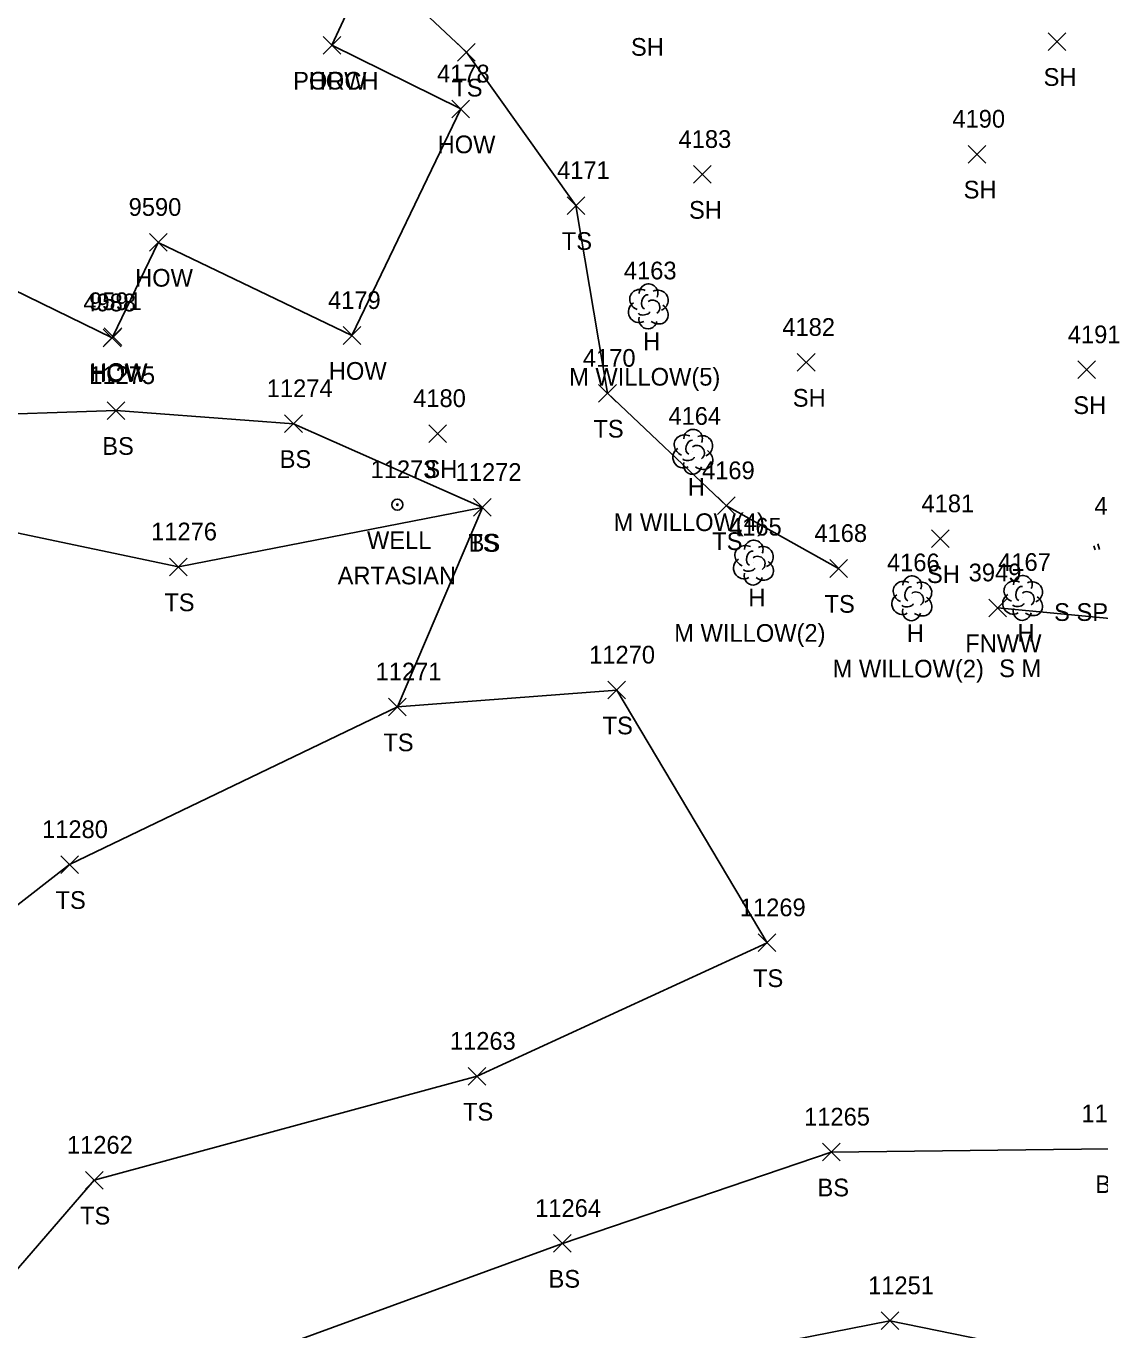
# Model space of a CAD drawing. Extents: x 1482574 to 1485769, y 580696 to 595649.
# Drawn here: x 1483580.3 to 1483701.6, y 583220.6 to 583367.9 of the extents above; entities that cross this region are included whole.
import ezdxf

# ---------------------------------------------------------------- set-up
doc = ezdxf.new("R2010")
doc.units = 0
for name, color, linetype in [('L_A', 7, 'Continuous'), ('L_C', 7, 'Continuous'), ('L_I', 7, 'Continuous'), ('L_TIC', 7, 'Continuous'), ('LBC', 7, 'Continuous'), ('LBF', 7, 'Continuous'), ('LELB', 7, 'Continuous'), ('LFNC', 7, 'Continuous'), ('LTC', 7, 'Continuous'), ('LTD', 7, 'Continuous'), ('U_A', 7, 'Continuous'), ('U_C', 7, 'Continuous'), ('U_I', 7, 'Continuous'), ('UWW', 7, 'Continuous')]:
    doc.layers.add(name, color=color, linetype=linetype)

msp = doc.modelspace()

# ---------------------------------------------------------------- linework, layer by layer
at = {"layer": 'L_TIC'}
for points in [[(1483613.84, 583364.72), (1483615.84, 583366.72)], [(1483615.84, 583364.72), (1483613.84, 583366.72)], [(1483613.84, 583364.72), (1483615.84, 583366.72)], [(1483615.84, 583364.72), (1483613.84, 583366.72)], [(1483695.74, 583365.14), (1483697.74, 583367.14)], [(1483697.74, 583365.14), (1483695.74, 583367.14)], [(1483629.03, 583363.94), (1483631.03, 583365.94)], [(1483631.03, 583363.94), (1483629.03, 583365.94)], [(1483628.4, 583357.53), (1483630.4, 583359.53)], [(1483630.4, 583357.53), (1483628.4, 583359.53)], [(1483686.71, 583352.42), (1483688.71, 583354.42)], [(1483688.71, 583352.42), (1483686.71, 583354.42)], [(1483655.69, 583350.13), (1483657.69, 583352.13)], [(1483657.69, 583350.13), (1483655.69, 583352.13)], [(1483641.4, 583346.61), (1483643.4, 583348.61)], [(1483643.4, 583346.61), (1483641.4, 583348.61)], [(1483594.22, 583342.46), (1483596.22, 583344.46)], [(1483596.22, 583342.46), (1483594.22, 583344.46)], [(1483589.02, 583331.67), (1483591.02, 583333.67)], [(1483591.02, 583331.67), (1483589.02, 583333.67)], [(1483589.11, 583331.81), (1483591.11, 583333.81)], [(1483591.11, 583331.81), (1483589.11, 583333.81)], [(1483616.11, 583331.94), (1483618.11, 583333.94)], [(1483618.11, 583331.94), (1483616.11, 583333.94)], [(1483667.41, 583328.9), (1483669.41, 583330.9)], [(1483669.41, 583328.9), (1483667.41, 583330.9)], [(1483699.1, 583328.07), (1483701.1, 583330.07)], [(1483701.1, 583328.07), (1483699.1, 583330.07)], [(1483644.97, 583325.41), (1483646.97, 583327.41)], [(1483646.97, 583325.41), (1483644.97, 583327.41)], [(1483589.46, 583323.46), (1483591.46, 583325.46)], [(1483591.46, 583323.46), (1483589.46, 583325.46)], [(1483609.5, 583321.98), (1483611.5, 583323.98)], [(1483611.5, 583321.98), (1483609.5, 583323.98)], [(1483625.8, 583320.87), (1483627.8, 583322.86)], [(1483627.8, 583320.87), (1483625.8, 583322.86)], [(1483630.84, 583312.52), (1483632.84, 583314.52)], [(1483632.84, 583312.52), (1483630.84, 583314.52)], [(1483630.84, 583312.52), (1483632.84, 583314.52)], [(1483632.84, 583312.52), (1483630.84, 583314.52)], [(1483658.4, 583312.71), (1483660.39, 583314.71)], [(1483660.39, 583312.71), (1483658.4, 583314.71)], [(1483682.57, 583308.98), (1483684.57, 583310.98)], [(1483684.57, 583308.98), (1483682.57, 583310.98)], [(1483596.5, 583305.8), (1483598.5, 583307.8)], [(1483598.5, 583305.8), (1483596.5, 583307.8)], [(1483671.09, 583305.62), (1483673.08, 583307.62)], [(1483673.08, 583305.62), (1483671.09, 583307.62)], [(1483689.03, 583301.17), (1483691.03, 583303.17)], [(1483691.03, 583301.17), (1483689.03, 583303.17)], [(1483646.01, 583291.89), (1483648.01, 583293.89)], [(1483648.01, 583291.89), (1483646.01, 583293.89)], [(1483621.24, 583289.98), (1483623.24, 583291.98)], [(1483623.24, 583289.98), (1483621.24, 583291.98)], [(1483621.24, 583289.98), (1483623.24, 583291.98)], [(1483623.24, 583289.98), (1483621.24, 583291.98)], [(1483584.21, 583272.17), (1483586.21, 583274.17)], [(1483586.21, 583272.17), (1483584.21, 583274.17)], [(1483663, 583263.34), (1483665, 583265.34)], [(1483665, 583263.34), (1483663, 583265.34)], [(1483630.24, 583248.26), (1483632.24, 583250.26)], [(1483632.24, 583248.26), (1483630.24, 583250.26)], [(1483670.25, 583239.7), (1483672.25, 583241.7)], [(1483672.25, 583239.7), (1483670.25, 583241.7)], [(1483586.99, 583236.52), (1483588.99, 583238.52)], [(1483588.99, 583236.52), (1483586.99, 583238.52)], [(1483639.87, 583229.38), (1483641.87, 583231.38)], [(1483641.87, 583229.38), (1483639.87, 583231.38)], [(1483676.87, 583220.65), (1483678.87, 583222.65)], [(1483678.87, 583220.65), (1483676.87, 583222.65)]]:
    msp.add_lwpolyline(points, dxfattribs=at)
at = {"layer": 'LBC'}
for points in [[(1483614.84, 583365.72), (1483629.4, 583358.53), (1483617.1, 583332.94)], [(1483595.22, 583343.46), (1483590.11, 583332.81)], [(1483617.1, 583332.94), (1483595.22, 583343.46)], [(1483570.72, 583342.09), (1483590.02, 583332.67)]]:
    msp.add_lwpolyline(points, dxfattribs=at)
at = {"layer": 'LBF'}
msp.add_lwpolyline([(1483587.58, 583390.09), (1483619.09, 583374.88), (1483614.84, 583365.72)], dxfattribs=at)
at = {"layer": 'LELB'}
for points in [[(1483672.08, 583306.62), (1483659.4, 583313.71), (1483645.97, 583326.41), (1483642.4, 583347.61), (1483630.03, 583364.94), (1483619.34, 583375.01), (1483587.64, 583390.32)], [(1483631.84, 583313.52), (1483610.5, 583322.98), (1483590.46, 583324.46), (1483554.82, 583323.25)], [(1483622.24, 583290.98), (1483631.84, 583313.52), (1483597.5, 583306.8), (1483569.02, 583312.79), (1483554.82, 583323.25)], [(1483559.44, 583204.52), (1483587.99, 583237.52), (1483631.24, 583249.26), (1483664, 583264.34), (1483647.01, 583292.89), (1483622.24, 583290.98), (1483585.21, 583273.17), (1483559.02, 583252.8), (1483537.11, 583265.27), (1483511.82, 583288.07), (1483510.48, 583240.48), (1483492.94, 583208.15)], [(1483754.24, 583194.32), (1483718.48, 583184.17), (1483687.9, 583163.9), (1483651.55, 583150.35), (1483624.97, 583140.56), (1483621.97, 583149.66), (1483641.52, 583162.4), (1483665.75, 583174.25), (1483688.95, 583192.65), (1483706.25, 583215.84), (1483677.87, 583221.65), (1483646.84, 583215.55), (1483607.15, 583199.05), (1483578.66, 583184.5), (1483568.65, 583194.97), (1483599.97, 583215.41), (1483640.87, 583230.38), (1483671.25, 583240.7), (1483702.63, 583241.07), (1483725.95, 583239.55)]]:
    msp.add_lwpolyline(points, dxfattribs=at)
at = {"layer": 'LFNC'}
msp.add_lwpolyline([(1483690.03, 583302.17), (1483708.71, 583300.4), (1483737.55, 583294.6), (1483760.68, 583294.44), (1483773.41, 583296.27), (1483784.28, 583296.14)], dxfattribs=at)
at = {"layer": 'LTC'}
for p, q in [((1483700.89, 583309.18), (1483701.04, 583308.72)), ((1483701.34, 583309.4), (1483701.55, 583308.75))]:
    msp.add_line(p, q, dxfattribs=at)
at = {"layer": 'LTD'}
for p, q in [((1483650.56, 583336.28), (1483650.56, 583336.28)), ((1483650.56, 583336.28), (1483650.56, 583336.28)), ((1483655.59, 583319.85), (1483655.59, 583319.85)), ((1483655.59, 583319.85), (1483655.59, 583319.85)), ((1483662.44, 583307.34), (1483662.44, 583307.34)), ((1483662.44, 583307.34), (1483662.44, 583307.34)), ((1483680.33, 583303.31), (1483680.33, 583303.31)), ((1483680.33, 583303.31), (1483680.33, 583303.31)), ((1483692.84, 583303.35), (1483692.84, 583303.35)), ((1483692.84, 583303.35), (1483692.84, 583303.35))]:
    msp.add_line(p, q, dxfattribs=at)
for centre in [(1483650.61, 583337.72), (1483655.64, 583321.29), (1483662.49, 583308.77), (1483680.38, 583304.74), (1483692.89, 583304.78)]:
    msp.add_arc(centre, 1.05, 335.5272, 180.9563, dxfattribs=at)
for centre, major_axis, ratio, start_param, end_param in [((1483649.77, 583336.95), (1.21, -0.51), 0.895232, 1.570796, 4.712389), ((1483651.6, 583336.87), (-1.14, -0.48), 0.949671, 1.570796, 4.712389), ((1483649.48, 583335.58), (0.58, -1.04), 0.959034, 3.141593, 6.283185), ((1483650.35, 583336.74), (-0.208, -0.792), 0.645439, 3.141593, 6.283185), ((1483651.06, 583336.12), (-0.5, 0.667), 0.989748, 3.141593, 6.283185), ((1483650.1, 583335.53), (-0.625, -0.083), 0.423636, 0, 3.141593), ((1483651.56, 583335.45), (-1.09, 0.79), 0.841452, 1.570796, 4.712389), ((1483650.56, 583334.78), (0.26, 1.06), 0.942809, 1.570796, 4.712389), ((1483654.8, 583320.52), (1.21, -0.51), 0.895232, 1.570796, 4.712389), ((1483655.38, 583320.31), (-0.208, -0.792), 0.645439, 3.141593, 6.283185), ((1483656.09, 583319.69), (-0.5, 0.667), 0.989748, 3.141593, 6.283185), ((1483656.63, 583320.44), (-1.14, -0.48), 0.949671, 1.570796, 4.712389), ((1483654.51, 583319.15), (0.58, -1.04), 0.959034, 3.141593, 6.283185), ((1483655.13, 583319.1), (-0.625, -0.083), 0.423636, 0, 3.141593), ((1483656.59, 583319.02), (-1.09, 0.79), 0.841452, 1.570796, 4.712389), ((1483655.59, 583318.35), (0.26, 1.06), 0.942809, 1.570796, 4.712389), ((1483661.65, 583308.01), (1.21, -0.51), 0.895232, 1.570796, 4.712389), ((1483662.23, 583307.8), (-0.208, -0.792), 0.645439, 3.141593, 6.283185), ((1483663.48, 583307.92), (-1.14, -0.48), 0.949671, 1.570796, 4.712389), ((1483661.36, 583306.63), (0.58, -1.04), 0.959034, 3.141593, 6.283185), ((1483662.94, 583307.17), (-0.5, 0.667), 0.989748, 3.141593, 6.283185), ((1483663.44, 583306.51), (-1.09, 0.79), 0.841452, 1.570796, 4.712389), ((1483662.44, 583305.84), (0.26, 1.06), 0.942809, 1.570796, 4.712389), ((1483661.98, 583306.59), (-0.625, -0.083), 0.423636, 0, 3.141593), ((1483679.54, 583303.97), (1.21, -0.51), 0.895232, 1.570796, 4.712389), ((1483680.12, 583303.77), (-0.208, -0.792), 0.645439, 3.141593, 6.283185), ((1483681.37, 583303.89), (-1.14, -0.48), 0.949671, 1.570796, 4.712389), ((1483692.05, 583304.01), (1.21, -0.51), 0.895232, 1.570796, 4.712389), ((1483692.63, 583303.81), (-0.208, -0.792), 0.645439, 3.141593, 6.283185), ((1483693.88, 583303.93), (-1.14, -0.48), 0.949671, 1.570796, 4.712389), ((1483679.25, 583302.6), (0.58, -1.04), 0.959034, 3.141593, 6.283185), ((1483680.83, 583303.14), (-0.5, 0.667), 0.989748, 3.141593, 6.283185), ((1483681.33, 583302.47), (-1.09, 0.79), 0.841452, 1.570796, 4.712389), ((1483691.76, 583302.64), (0.58, -1.04), 0.959034, 3.141593, 6.283185), ((1483692.38, 583302.6), (-0.625, -0.083), 0.423636, 0, 3.141593), ((1483693.34, 583303.18), (-0.5, 0.667), 0.989748, 3.141593, 6.283185), ((1483693.84, 583302.51), (-1.09, 0.79), 0.841452, 1.570796, 4.712389), ((1483680.33, 583301.81), (0.26, 1.06), 0.942809, 1.570796, 4.712389), ((1483679.87, 583302.56), (-0.625, -0.083), 0.423636, 0, 3.141593), ((1483692.84, 583301.85), (0.26, 1.06), 0.942809, 1.570796, 4.712389)]:
    msp.add_ellipse(centre, major_axis=major_axis, ratio=ratio, start_param=start_param, end_param=end_param, dxfattribs=at)
at = {"layer": 'UWW'}
for radius in [0.625, 0.0833]:
    msp.add_circle((1483622.24, 583313.83), radius, dxfattribs=at)

# ---------------------------------------------------------------- texts
at = {"layer": 'L_A'}
for s, p in [('SH', (1483648.62, 583364.54)), ('SH', (1483695.23, 583361.14)), ('PORCH', (1483610.46, 583360.72)), ('HOW', (1483612.22, 583360.72)), ('TS', (1483628.44, 583359.94)), ('HOW', (1483626.78, 583353.53)), ('SH', (1483686.2, 583348.42)), ('SH', (1483655.18, 583346.13)), ('TS', (1483640.81, 583342.61)), ('HOW', (1483592.61, 583338.46)), ('H', (1483649.99, 583331.28)), ('HOW', (1483587.41, 583327.67)), ('HOW', (1483587.49, 583327.81)), ('HOW', (1483614.49, 583327.94)), ('SH', (1483666.9, 583324.9)), ('SH', (1483698.59, 583324.07)), ('TS', (1483644.38, 583321.41)), ('BS', (1483588.9, 583319.46)), ('BS', (1483608.94, 583317.98)), ('SH', (1483625.29, 583316.86)), ('H', (1483655.03, 583314.85)), ('TS', (1483630.25, 583308.52)), ('BS', (1483630.28, 583308.52)), ('TS', (1483657.8, 583308.71)), ('SH', (1483682.06, 583304.98)), ('H', (1483661.88, 583302.34)), ('TS', (1483595.91, 583301.8)), ('TS', (1483670.49, 583301.62)), ('H', (1483679.77, 583298.31)), ('H', (1483692.27, 583298.35)), ('FNWW', (1483686.38, 583297.17)), ('TS', (1483645.42, 583287.89)), ('TS', (1483620.65, 583285.98)), ('TS', (1483620.65, 583285.98)), ('TS', (1483583.62, 583268.17)), ('TS', (1483662.41, 583259.34)), ('TS', (1483629.65, 583244.26)), ('BS', (1483701.07, 583236.07)), ('BS', (1483669.69, 583235.7)), ('TS', (1483586.39, 583232.52)), ('BS', (1483639.31, 583225.38))]:
    msp.add_text(s, height=2, dxfattribs=at).set_placement(p)
at = {"layer": 'L_C'}
for s, p in [('M WILLOW(5)', (1483641.63, 583327.28)), ('M WILLOW(4)', (1483646.66, 583310.85)), ('S SPRUCE', (1483696.42, 583300.7)), ('M WILLOW(2)', (1483653.51, 583298.34)), ('M WILLOW(2)', (1483671.4, 583294.31)), ('S M', (1483690.21, 583294.35))]:
    msp.add_text(s, height=2, dxfattribs=at).set_placement(p)
at = {"layer": 'L_I'}
for s, p in [('4178', (1483626.71, 583361.53)), ('4190', (1483684.93, 583356.42)), ('4183', (1483654, 583354.13)), ('4171', (1483640.27, 583350.61)), ('9590', (1483591.88, 583346.46)), ('4163', (1483647.82, 583339.28)), ('4988', (1483586.76, 583335.67)), ('9591', (1483587.41, 583335.81)), ('4179', (1483614.4, 583335.94)), ('4182', (1483665.72, 583332.9)), ('4191', (1483697.97, 583332.07)), ('4170', (1483643.19, 583329.41)), ('11275', (1483587.43, 583327.46)), ('11274', (1483607.48, 583325.98)), ('4180', (1483624.02, 583324.86)), ('4164', (1483652.85, 583322.85)), ('11272', (1483628.82, 583316.52)), ('11272', (1483628.82, 583316.52)), ('4169', (1483656.65, 583316.71)), ('4181', (1483681.44, 583312.98)), ('4193', (1483700.97, 583312.7)), ('11276', (1483594.42, 583309.8)), ('4165', (1483659.7, 583310.34)), ('4168', (1483669.34, 583309.62)), ('4166', (1483677.54, 583306.31)), ('3949', (1483686.77, 583305.17)), ('4167', (1483690.1, 583306.35)), ('11270', (1483643.9, 583295.89)), ('11271', (1483619.78, 583293.98)), ('11271', (1483619.78, 583293.98)), ('11280', (1483582.1, 583276.17)), ('11269', (1483660.92, 583267.34)), ('11263', (1483628.17, 583252.26)), ('11265', (1483668.18, 583243.7)), ('11266', (1483699.51, 583244.07)), ('11262', (1483584.91, 583240.52)), ('11264', (1483637.8, 583233.38)), ('11251', (1483675.41, 583224.65))]:
    msp.add_text(s, height=2, dxfattribs=at).set_placement(p)
at = {"layer": 'U_A'}
msp.add_text('WELL', height=2, dxfattribs=at).set_placement((1483618.8, 583308.83))
at = {"layer": 'U_C'}
msp.add_text('ARTASIAN', height=2, dxfattribs=at).set_placement((1483615.49, 583304.83))
at = {"layer": 'U_I'}
msp.add_text('11273', height=2, dxfattribs=at).set_placement((1483619.21, 583316.83))

doc.saveas('drawing.dxf')
